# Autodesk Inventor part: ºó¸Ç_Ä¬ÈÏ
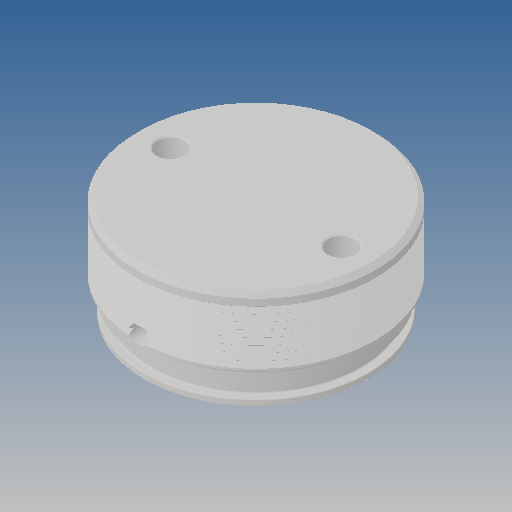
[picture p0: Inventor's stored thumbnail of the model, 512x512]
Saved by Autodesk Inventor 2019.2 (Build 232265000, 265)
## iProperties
Created: 2012-03
Part Number: ºó¸Ç_Ä¬ÈÏ
Material: Ogólny
Document SubType Name: Modeling
Designer: CADENGINEERING4
Density: 1 g/cm^3
Appearance: Domyślna
Author: CADENGINEERING4
Revision Number: ÈÎºÎ
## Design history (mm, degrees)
feature "NONE"
node "Bryła1"
